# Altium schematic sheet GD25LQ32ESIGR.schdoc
size 127 x 101 mm
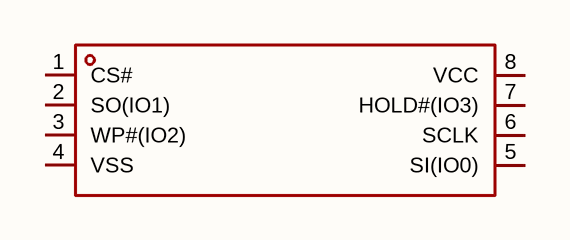
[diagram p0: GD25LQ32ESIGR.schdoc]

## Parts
U?  gd25lq32esigr  [SOP-8_L5.3-W5.3-P1.27-LS7.9-BL]  (value not drawn)

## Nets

Not connected (* = marked no-connect by the designer): U? 1(CS#) 2(SO(IO1)) 3(WP#(IO2)) 4(VSS) 5(SI(IO0)) 6(SCLK) 7(HOLD#(IO3)) 8(VCC)

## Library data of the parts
U? = gd25lq32esigr: 接口类型:SPI;存储容量:32Mbit;时钟频率(fc):133MHz;; Manufacturer: GigaDevice(兆易创新); AddInBom: yes; ModelId: 72eaeed142424588879d6a198b07ab72; ModelTransform: 207.67675,311.023,0,0,0,0,0,0,0; Interface: SPI; Memory Size: 32Mbit; Clock Frequency: 133MHz; Voltage - Supply: 1.65V~2V; Standby Supply Current: 10uA; Program / Erase Cycles: 100000次; Page Programming Time (Tpp): 400us; Data Retention - TDR (Year): 20年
